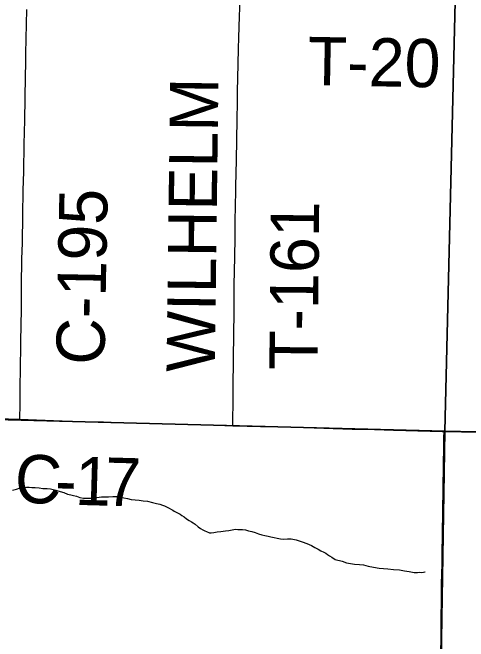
# Model space of a CAD drawing. Extents: x 0 to 34, y 0 to 22.
# Drawn here: x 4.847 to 5.383, y 15.12 to 15.859 of the extents above; entities that cross this region are included whole.
import ezdxf

# ---------------------------------------------------------------- set-up
doc = ezdxf.new("R2010")
doc.units = 0
for name, color, linetype in [('GM_X_County_Road', 7, 'Continuous'), ('GM_X_County_Road_Text', 7, 'Continuous'), ('GM_X_Minor_River', 7, 'Continuous'), ('GM_X_Section', 7, 'Continuous'), ('GM_X_Township_Road', 7, 'Continuous'), ('GM_X_Township_Road_Text', 7, 'Continuous')]:
    doc.layers.add(name, color=color, linetype=linetype)

msp = doc.modelspace()

# ---------------------------------------------------------------- linework, layer by layer
at = {"layer": 'GM_X_County_Road'}
for points in [[(4.85517, 15.38099), (4.85546, 15.39898), (4.85564, 15.40766), (4.85573, 15.41697), (4.85575, 15.42381), (4.85584, 15.43562), (4.85609, 15.44681), (4.85641, 15.46172), (4.85649, 15.46918), (4.85688, 15.49466), (4.85698, 15.50709), (4.85719, 15.52139), (4.85728, 15.53816), (4.85766, 15.56926), (4.85815, 15.58852), (4.85876, 15.621), (4.85932, 15.65028), (4.85973, 15.67241), (4.86038, 15.70473), (4.86091, 15.7327), (4.86197, 15.78429), (4.8623, 15.80042), (4.86232, 15.8029), (4.86246, 15.81132), (4.86332, 15.86297)], [(4.82832, 15.38173), (4.85517, 15.38099)], [(4.85517, 15.38099), (4.87464, 15.38009), (4.92496, 15.37849), (4.95355, 15.37776), (4.97219, 15.37732), (4.9902, 15.37677), (5.02873, 15.37569), (5.07719, 15.37422), (5.10565, 15.37339)], [(5.10565, 15.37339), (5.10703, 15.37335), (5.13809, 15.37256), (5.17911, 15.37157), (5.24621, 15.36946), (5.27232, 15.36883), (5.29469, 15.36822), (5.32327, 15.36751), (5.35186, 15.36663), (5.35423, 15.36659)], [(5.35013, 15.07675), (5.35086, 15.1277), (5.35126, 15.18738), (5.35174, 15.21037), (5.35186, 15.22279), (5.35223, 15.24578), (5.35346, 15.32657), (5.3538, 15.34895), (5.35406, 15.35952), (5.35423, 15.36659)], [(5.35423, 15.36659), (5.39474, 15.36584), (5.41276, 15.36534), (5.43452, 15.36512), (5.47243, 15.3645), (5.55014, 15.36373), (5.5837, 15.36322), (5.60298, 15.36295), (5.64772, 15.3624), (5.69062, 15.36191), (5.73225, 15.36116), (5.77453, 15.36051), (5.80124, 15.3603), (5.8533, 15.35976)]]:
    msp.add_lwpolyline(points, dxfattribs=at)
at = {"layer": 'GM_X_Minor_River'}
for points in [[(4.84645, 15.29741), (4.85144, 15.29877), (4.85568, 15.30015), (4.85989, 15.30077), (4.86294, 15.30105), (4.86599, 15.30095), (4.86941, 15.30084), (4.87321, 15.30071), (4.87777, 15.30018), (4.88232, 15.29965), (4.88727, 15.29949), (4.89144, 15.29897), (4.89447, 15.29849), (4.89749, 15.29763), (4.90277, 15.29593), (4.90692, 15.29465), (4.91143, 15.29298), (4.91521, 15.2921), (4.91823, 15.29124), (4.92201, 15.29035), (4.92578, 15.28909), (4.92994, 15.28819), (4.93489, 15.28802), (4.93985, 15.28824), (4.94558, 15.28881), (4.95132, 15.28977), (4.95932, 15.28988), (4.96466, 15.29009), (4.96922, 15.28993), (4.9734, 15.28941), (4.97756, 15.28852), (4.98172, 15.28762), (4.98626, 15.28671), (4.99081, 15.28618), (4.99575, 15.28563), (5.0003, 15.2851), (5.00523, 15.28456), (5.01128, 15.28322), (5.01581, 15.28193), (5.01997, 15.28103), (5.02298, 15.27979), (5.02524, 15.27895), (5.02712, 15.27813), (5.02938, 15.27729)], [(5.02938, 15.27729), (5.03499, 15.27407), (5.03685, 15.27286), (5.0391, 15.27165), (5.04134, 15.27043), (5.04359, 15.26922), (5.04582, 15.26762), (5.04844, 15.26601), (5.05141, 15.26363), (5.0544, 15.26201), (5.05702, 15.2604), (5.05889, 15.2592), (5.0615, 15.25759), (5.06482, 15.25444), (5.06781, 15.25244), (5.07042, 15.25083), (5.07267, 15.24961), (5.07493, 15.24878), (5.07832, 15.24752), (5.08022, 15.24746), (5.08327, 15.24774), (5.08748, 15.24836), (5.09169, 15.24898), (5.09704, 15.24957), (5.10087, 15.2502), (5.10508, 15.25082), (5.10891, 15.25146), (5.11157, 15.25137), (5.11462, 15.25127), (5.11728, 15.25118), (5.12069, 15.25069), (5.12409, 15.24981), (5.12825, 15.24892), (5.13202, 15.24765), (5.13577, 15.24601), (5.13993, 15.24511), (5.14333, 15.24423), (5.14712, 15.24335), (5.15051, 15.24247), (5.16187, 15.2402), (5.16567, 15.24007), (5.16987, 15.24031), (5.17443, 15.24016), (5.18012, 15.23921), (5.18727, 15.2367), (5.19292, 15.23461), (5.19818, 15.23253), (5.2023, 15.23011), (5.20604, 15.22809), (5.2094, 15.22607), (5.21278, 15.22444), (5.21502, 15.22322), (5.21689, 15.22202), (5.2195, 15.22041), (5.22212, 15.2188), (5.22622, 15.216), (5.23415, 15.21384), (5.23943, 15.21214), (5.24397, 15.21123), (5.24889, 15.21031), (5.25459, 15.21012), (5.25953, 15.20958), (5.26482, 15.20826), (5.27125, 15.20691), (5.27769, 15.20593), (5.28301, 15.20538), (5.28794, 15.20484), (5.29478, 15.20423), (5.30161, 15.20362), (5.30768, 15.20266), (5.31298, 15.20173), (5.31904, 15.20076), (5.32284, 15.20064), (5.32552, 15.20093), (5.3278, 15.20085), (5.3301, 15.20116), (5.33163, 15.20149), (5.33201, 15.20148)]]:
    msp.add_lwpolyline(points, dxfattribs=at)
at = {"layer": 'GM_X_Section'}
for points in [[(4.38456, 16.43152), (5.38005, 16.41012), (5.35524, 15.36699), (4.35758, 15.39266)], [(5.38005, 16.41012), (5.38574, 16.41038), (6.38559, 16.38675), (6.36308, 15.34539), (5.35524, 15.36699)], [(5.35524, 15.36699), (5.3389, 14.36266), (4.33594, 14.38845), (4.35758, 15.39266)], [(5.35524, 15.36699), (6.36308, 15.34539), (6.34437, 14.33999), (5.3389, 14.36266)]]:
    msp.add_lwpolyline(points, close=True, dxfattribs=at)
at = {"layer": 'GM_X_Township_Road'}
msp.add_lwpolyline([(5.10565, 15.37339), (5.10574, 15.3812), (5.10593, 15.39985), (5.10611, 15.41664), (5.10664, 15.45331), (5.10714, 15.5074), (5.10745, 15.53786), (5.10765, 15.55651), (5.10794, 15.57082), (5.10814, 15.58138), (5.10828, 15.58511), (5.10862, 15.61992), (5.10879, 15.62613), (5.10939, 15.65533), (5.10998, 15.68579), (5.11088, 15.73363), (5.11123, 15.7541), (5.11134, 15.76641), (5.11198, 15.79865), (5.11236, 15.81723), (5.11272, 15.82958), (5.11344, 15.85502), (5.1138, 15.86464), (5.11398, 15.87372)], dxfattribs=at)

# ---------------------------------------------------------------- texts
at = {"layer": 'GM_X_County_Road_Text'}
for s, height, rotation, p in [('C-195', 0.056818, 88.91602, (4.95468, 15.44467)), ('C', 0.05682, 356.94639, (4.84808, 15.2836)), ('1', 0.05682, 358.37026, (4.91954, 15.28032)), ('7', 0.05682, 358.43236, (4.95459, 15.27933)), ('-', 0.05682, 358.20535, (4.89604, 15.28106))]:
    msp.add_text(s, height=height, rotation=rotation, dxfattribs=at).set_placement(p)
at = {"layer": 'GM_X_Township_Road_Text'}
for s, rotation, p in [('T-20', 358.95093, (5.19329, 15.77416)), ('WILHELM', 89.27115, (5.08447, 15.43622)), ('T-161', 89.44598, (5.20542, 15.43875))]:
    msp.add_text(s, height=0.056818, rotation=rotation, dxfattribs=at).set_placement(p)

doc.saveas('drawing.dxf')
